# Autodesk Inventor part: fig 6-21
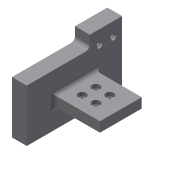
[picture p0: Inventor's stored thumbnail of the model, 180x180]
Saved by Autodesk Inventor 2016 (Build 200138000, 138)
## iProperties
Created: 2004-05
Part Number: fig 6-21
Document SubType Name: Modeling
Designer: CADCIM Technologies
Manufacturer: Standard
Standards Organization: Custom
Density: 1 g/cm^3
Material: Generic
Appearance: Default
Author: CADCIM Technologies
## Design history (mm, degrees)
node "Sketch1"
sketch "Sketch2"
  geometry: L1 (0, 0)-(0, 26.557); L2 (0, 26.557)-(31.986, 26.557); L3 (31.986, 26.557)-(31.986, 32.916); L4 (31.986, 32.916)-(48.42, 32.916); L5 (48.42, 32.916)-(48.42, 0); L6 (48.42, 0)-(0, 0)
  constraints: 12 end point, 4 parallel, 1 perpendicular, 1 vertical
extrude "Extrusion1" new body sketch "Sketch2" distance "d0" = 7.5; taper "d1" = 0 deg
workplane "Work Plane1"
sketch "Sketch3"
  geometry: L1 (7.5, 35.088)-(30.78, 35.088); L2 (30.78, 35.088)-(30.78, 13.871); L3 (30.78, 13.871)-(7.5, 13.871); L4 (7.5, 31.986)-(7.5, 48.42) reference; L5 (7.5, 0)-(7.5, 31.986) reference
  constraints: 6 end point, 2 point on line, 1 horizontal, 1 parallel, 1 perpendicular
extrude "Extrusion2" join sketch "Sketch3" distance "d3" = 5; taper "d4" = 0 deg
fillet "Fillet2" dims "d7" = 2
fillet "Fillet3" dims "d8" = 2
hole "Hole1" diameter "d11" = 3; stored, may be unused: countersink angle "d15" = 90 deg, drill point angle "d17" = 118 deg; dims "d9" = 7, "d10" = 16, "d12" = 6, "d13" = 4, "d14" = 2, "d16" = 8
pattern_linear "Rectangular Pattern1" dims "d20" = 7, "d23" = 7
hole "Hole2" diameter "d26" = 2; stored, may be unused: countersink angle "d30" = 90 deg, drill point angle "d32" = 118 deg; dims "d24" = 5, "d25" = 7, "d27" = 6, "d28" = 3, "d29" = 1, "d31" = 8
pattern_linear "Rectangular Pattern2" dims "d35" = 7
body "Solid1"
other parameters: "d2" = -11
